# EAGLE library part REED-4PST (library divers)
Reed relay 4PST Electronic applications company 044AY*250DAC 51190509-002
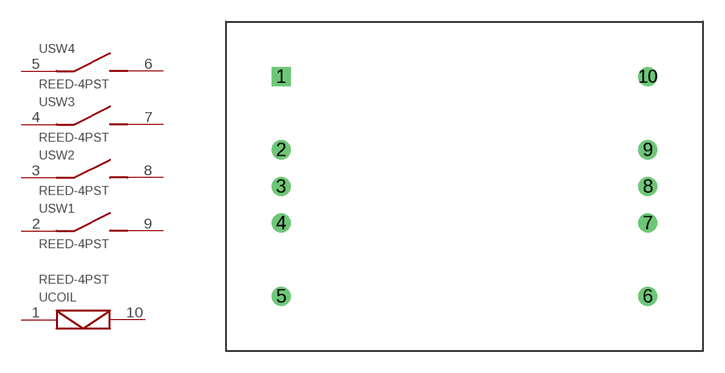
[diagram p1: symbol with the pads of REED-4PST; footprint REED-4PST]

Designator prefix -; gates COIL=REED-COIL SW1=REED-SW SW2=REED-SW SW3=REED-SW SW4=REED-SW

## REED-4PST  [REED-4PST]
1  COIL:COIL1  pas
2  SW1:SW1  pas
3  SW2:SW1  pas
4  SW3:SW1  pas
5  SW4:SW1  pas
6  SW4:SW2  pas
7  SW3:SW2  pas
8  SW2:SW2  pas
9  SW1:SW2  pas
10  COIL:COIL2  pas

## Footprint REED-4PST (pad centres in mm)
Reed relay 4PST Electronic applications company 044AY*250DAC 51190509-002
drill 0.813 square: 1 0,15.24
drill 0.813 round: 2 0,10.16; 3 0,7.62; 4 0,5.08; 5 0,0; 6 25.4,0; 7 25.4,5.08; 8 25.4,7.62; 9 25.4,10.16; 10 25.4,15.24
